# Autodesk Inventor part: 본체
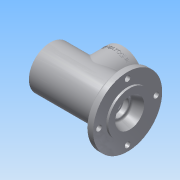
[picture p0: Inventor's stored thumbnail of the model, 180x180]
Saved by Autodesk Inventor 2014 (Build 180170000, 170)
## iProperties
Created: 2016-08
Part Number: 본체
Material: 알루미늄 6061
Document SubType Name: Modeling
Designer: 703-04
Density: 2.71 g/cm^3
Appearance: 알루미늄 - 평지
Mass: 730.839 g
Surface Area: 616.864 cm^2
Volume: 269.682 cm^3
Author: 703-04
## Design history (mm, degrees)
sketch "스케치1"
  geometry: C1 r 50 at (0, 0); 1 further point
  constraints: 1 centre point, 1 coincident
  dimensions: "d0" = 100 diameter of C1
extrude "돌출1" new body sketch "스케치1" distance "d1" = 10; taper "d2" = 0 deg
sketch "스케치2"
  geometry: C1 r 50 at (0, 0) reference; C2 r 31 at (0, 0)
  constraints: 1 centre point, 1 coincident
  dimensions: "d3" = 62 diameter of C2
extrude "돌출2" join sketch "스케치2" distance "d4" = 3; taper "d5" = 0 deg
sketch "스케치3" dims "d6" = 83
  geometry: L1 (0, 0)-(0, 41.5); C1 r 50 at (0, 0) reference; C2 r 4 at (0, 41.5)
  constraints: 2 coincident, 2 end point, 1 centre point, 1 vertical, 1 vertical alignment, 2 other
  dimensions: "d7" = 8 diameter of C2
extrude "돌출3" cut sketch "스케치3" stored distance "d9" = 3; taper "d10" = 0 deg
fillet "모깎기1" dims "d14" = 3
sketch "스케치4"
  geometry: C1 r 47 at (0, 0) reference; C2 r 31 at (0, 0)
  constraints: 1 centre point, 1 coincident
  dimensions: "d15" = 62 diameter of C2
extrude "돌출4" join sketch "스케치4" distance "d16" = 102; taper "d17" = 0 deg
sketch "스케치5"
  geometry: L1 (13, -31)-(13, 31) reference; L2 (13, 0)-(13, 21); L3 (13, 0)-(-1, 0); L4 (-1, 0)-(-1, 16); L5 (0, -47)-(0, 47) reference; L6 (-1, 16)-(13, 21); 1 further point
  constraints: 8 end point, 1 midpoint, 1 parallel, 1 perpendicular, 1 point on line
  dimensions: "d19" = 14 distance of L2.start L3.end; "d20" = 42 diameter of L2.end L3; "d21" = 32 diameter of L4.end L3
revolve "회전1" sketch "스케치5" stored, may be unused: angle "d22" = 90 deg
sketch "스케치6"
  geometry: C1 r 16 at (0, 0) reference; C2 r 12.5 at (0, 0)
  constraints: 1 centre point, 1 coincident
  dimensions: "d24" = 25 diameter of C2
extrude "돌출5" cut sketch "스케치6" distance "d25" = 7.3; taper "d26" = 0 deg
fillet "모깎기2" dims "d27" = 3
fillet "모깎기3" dims "d31" = 0.3
sketch "스케치7"
  geometry: C1 r 12.2 at (0, 0) reference; C2 r 10 at (0, 0)
  constraints: 1 centre point, 1 coincident
  dimensions: "d32" = 20 diameter of C2
extrude "돌출6" cut sketch "스케치7" distance "d33" = 2.7; taper "d34" = 0 deg
sketch "스케치8"
  geometry: C1 r 31 at (0, 0) reference
hole "구멍1" sketch "스케치8" at (0, 0) diameter "d35" = 40.376; stored, may be unused: countersink angle "d39" = 90 deg, drill point angle "d41" = 0 deg; dims "d36" = 6, "d37" = 4, "d38" = 2, "d40" = 9
chamfer "모따기2" distance "d44" = 0.7; stored, may be unused: second distance "d45" = 2, angle "d46" = 30 deg
sketch "스케치11"
  geometry: L1 (-93, 20.188)-(-93, -20.188) reference; L2 (-93, 0)-(-11, 0); L3 (-11, 10)-(-11, -10) reference; L4 (-11, 0)-(-11, 16.5); L5 (-11, 16.5)-(-16, 16.5); L6 (-16, 16.5)-(-16, 17.5); L7 (-93, 0)-(-93, 24); L8 (-93, 24)-(-90, 24); L9 (-90, 24)-(-90, 20); L10 (-90, 20)-(-81, 20); L11 (-102, -20.188)-(-102, 20.188) reference; L12 (-81, 20)-(-81, 17.5); L13 (-81, 17.5)-(-77.75, 17.5); L14 (-77.75, 17.5)-(-77.75, 18.5); L15 (-77.75, 18.5)-(-76, 18.5); L16 (-76, 18.5)-(-76, 17.5); L17 (0, 31)-(-102, 31) reference; L18 (-65, 26)-(-27, 26); L19 (-65, 26)-(-65, 17.5); L20 (-27, 26)-(-27, 17.5); L21 (-76, 17.5)-(-65, 17.5); L22 (-27, 17.5)-(-16, 17.5); 1 further point
  constraints: 36 end point, 10 perpendicular, 4 parallel, 2 midpoint, 1 point on line
  dimensions: "d47" = 33 diameter of L4.end L2; "d48" = 5 distance of L4.end L5.end; "d54" = 35 diameter of L6.end L2; "d55" = 48 diameter of L7.end L2; "d56" = 3 distance of L7.end L8.end; "d57" = 40 diameter of L9.end L2; "d58" = 21 distance from line of L10.end L11; "d59" = 35 diameter of L12.end L2; "d60" = 1.75 distance of L14.end L15.end; "d61" = 35 diameter of L16.end L2; "d62" = 37 diameter of L15 L2; "d63" = 26 distance from line of L11 L16.end; "d65" = 38 distance of L18.start L18.end; "d67" = 8.5 distance of L18.start L19.end; "d110" = 52 diameter of L18 L2; "d111" = 37.48333 distance of point (0, 0) L18.end
revolve "회전2" sketch "스케치11" stored, may be unused: angle "d69" = 90 deg
fillet "모깎기4" dims "d70" = 3
fillet "모깎기5" dims "d71" = 0.3
chamfer "모따기3" distance "d72" = 1; stored, may be unused: second distance "d73" = 2, angle "d74" = 30 deg
node "작업 평면1"
sketch "스케치12"
  geometry: L1 (102, -21.188)-(102, 21.188) reference; L2 (102, 0)-(46, 0); C1 r 30 at (46, 0); 1 further point
  constraints: 2 end point, 1 centre point, 1 coincident, 1 midpoint, 1 perpendicular
  dimensions: "d77" = 56 distance of L2.start L2.end; "d78" = 60 diameter of C1
extrude "돌출7" join sketch "스케치12" stored distance "d79" = 3; taper "d80" = 0 deg
sketch "스케치13"
  geometry: C1 r 30 at (0, 0) reference; C2 r 19 at (0, 0); 1 further point
  constraints: 1 centre point, 1 coincident
  dimensions: "d81" = 38 diameter of C2
extrude "돌출8" cut sketch "스케치13" stored distance "d82" = 3; taper "d83" = 0 deg
sketch "스케치15" dims "d84" = 48
  geometry: L1 (0, 0)-(0, 24); C1 r 30 at (0, 0) reference; 1 further point
  constraints: 2 end point, 1 coincident, 1 vertical, 1 vertical alignment, 2 other
hole "구멍2" sketch "스케치15" at (0, 24) diameter "d85" = 3.242; stored, may be unused: countersink angle "d89" = 90 deg, drill point angle "d91" = 118 deg; dims "d86" = 8, "d87" = 4, "d88" = 2, "d90" = 10
chamfer "모따기4" distance "d95" = 1; stored, may be unused: second distance "d96" = 2, angle "d97" = 30 deg
fillet "모깎기7" dims "d99" = 3
node "작업 평면2"
sketch "스케치17"
  geometry: L1 (-30, 0)-(30, 0) reference; L2 (0, 0)-(0, -10); L3 (1.621, -10)-(-1.621, -10) reference; 2 further points
  constraints: 2 coincident, 2 end point, 2 midpoint, 1 other
  dimensions: "d102" = 10 distance of L2.start L2.end (derived)
feature "엠보싱1" sketch "스케치17" dims "d103" = 0.5, "d104" = 0
fillet "모깎기9" dims "d106" = 3
node "솔리드1"
pattern_circular "원형 패턴1" dims angle "d12" = 360 deg
pattern_circular "원형 패턴2" dims angle "d93" = 360 deg
other parameters: "d75" = 49
